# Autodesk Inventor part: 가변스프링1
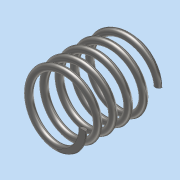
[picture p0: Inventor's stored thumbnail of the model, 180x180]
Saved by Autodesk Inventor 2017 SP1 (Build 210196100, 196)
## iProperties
Part Number: 가변스프링1
Material: 스테인레스 스틸
Document SubType Name: Modeling
Designer: MRC
Density: 8 g/cm^3
Appearance: 반연마
Mass: 6.97832 g
Surface Area: 17.713 cm^2
Volume: 0.872289 cm^3
Author: MRC
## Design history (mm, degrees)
sketch "스케치1"
  geometry: L1 (0, 0)-(0, 22.5); L2 (0, 22.5)-(9, 22.5); L3 (0, 0)-(9, 0); C1 r 1 at (9, 0)
  constraints: 6 end point, 1 centre point, 1 coincident, 1 horizontal, 1 perpendicular, 1 vertical
  dimensions: "d0" = 22.5 distance of L1.start L1.end (derived); "d1" = 9 distance of L1.end L2.end; "d2" = 9 distance of L1.start L3.end; "d3" = 2 diameter of C1
feature "코일1" pitch "d4" = 10; turns "d6" = 5; dims "d5" = 22.5 (= d0), "d7" = 0, angle "d8" = 90 deg, angle "d9" = 90 deg, "d10" = 0, "d11" = 0
sketch "스케치2"
  geometry: L1 (22.5, 15)-(0, 15); L2 (0, 15)-(0, -15); L3 (0, -15)-(22.5, -15); L4 (22.5, -15)-(22.5, 15); 2 further points
  constraints: 8 end point, 2 midpoint, 2 parallel, 1 coincident, 1 horizontal, 1 perpendicular
  dimensions: "d12" = 30 distance of L3.end L1.start; "d13" = 22.5 distance of L1.start L1.end (= d0)
extrude "돌출2" sketch "스케치2" stored distance "d16" = 0; taper "d17" = 0 deg
node "솔리드1"
